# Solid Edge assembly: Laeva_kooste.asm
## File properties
Author: Olev
Template: Normal.asm
Last saved by: haldur
Revision: 35
Application: Solid Edge
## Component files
Torn.par
Vent_karp.psm
Poort_ylemine.psm
Poort_kyljel.psm
Laeva_kere_1.par
Pealisehitus.par
Tyyr.par
ver_kruvi.par
Peakruvi.par
Katus_1.psm
Poort_taga.psm
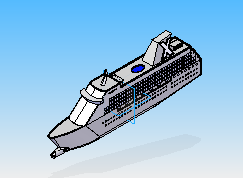
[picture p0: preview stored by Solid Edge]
